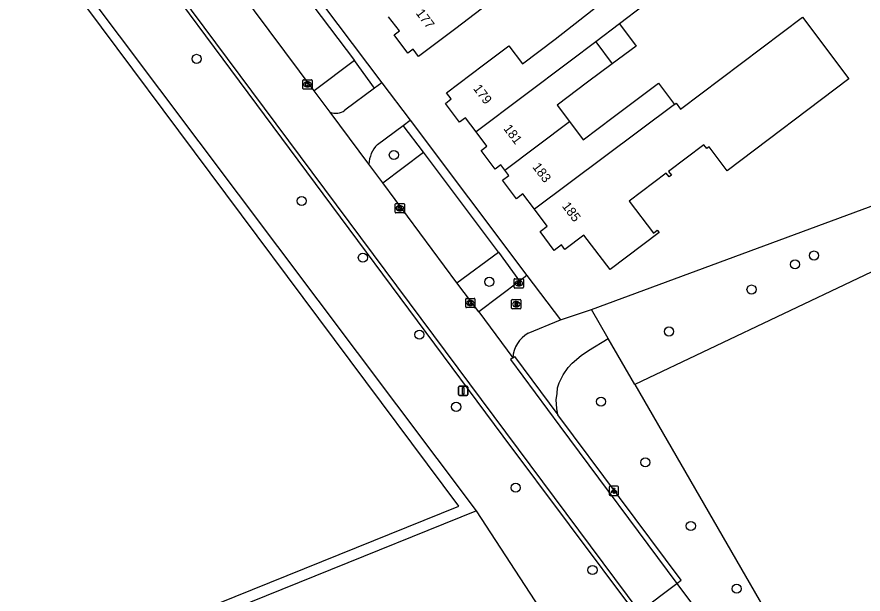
# Model space of a CAD drawing. Extents: x 164494 to 166241, y 382475 to 384494.
# Drawn here: x 165007.7 to 165098.7, y 383132.9 to 383195 of the extents above; entities that cross this region are included whole.
import ezdxf

# ---------------------------------------------------------------- set-up
doc = ezdxf.new("R2010")
doc.units = 0
for name, color, linetype in [('IMGEO_Berm_halfverhard', 7, 'Continuous'), ('IMGEO_Boom', 7, 'Continuous'), ('IMGEO_Bouwland', 7, 'Continuous'), ('IMGEO_Brandkraan', 7, 'Continuous'), ('IMGEO_Haag', 7, 'Continuous'), ('IMGEO_Hek', 7, 'Continuous'), ('IMGEO_Kolk', 7, 'Continuous'), ('IMGEO_Lichtpunt', 7, 'Continuous'), ('IMGEO_Loofbos', 7, 'Continuous'), ('IMGEO_Pand', 7, 'Continuous'), ('IMGEO_Pand_nummerreeks', 7, 'Continuous'), ('IMGEO_Parkeervlak_open', 7, 'Continuous'), ('IMGEO_Rijbaan_lokaal_gesloten', 7, 'Continuous'), ('IMGEO_Rijbaan_lokaal_onverhard', 7, 'Continuous'), ('IMGEO_Rioolput', 7, 'Continuous'), ('IMGEO_Verkeersbordpaal', 7, 'Continuous'), ('IMGEO_Voetpad_open', 7, 'Continuous')]:
    doc.layers.add(name, color=color, linetype=linetype)

msp = doc.modelspace()

# ---------------------------------------------------------------- linework, layer by layer
at = {"layer": 'IMGEO_Berm_halfverhard'}
for points in [[(165010.162, 383216.934), (165012.663, 383213.574), (165041.519, 383174.67), (165059.934, 383149.875), (165074.189, 383130.821), (165074.54, 383131.069)], [(165078.641, 383134.022), (165079.122, 383134.381), (165065.842, 383152.183)]]:
    msp.add_lwpolyline(points, dxfattribs=at)
at = {"layer": 'IMGEO_Boom'}
for centre in [(165027.003, 383190.44), (165048.216, 383180.108), (165038.31, 383175.163), (165044.883, 383169.068), (165093.391, 383169.297), (165091.349, 383168.347), (165058.474, 383166.472), (165086.672, 383165.641), (165050.966, 383160.792), (165077.792, 383161.13), (165070.494, 383153.587), (165054.914, 383153.031), (165075.248, 383147.061), (165061.314, 383144.337), (165080.143, 383140.228), (165069.575, 383135.482), (165085.071, 383133.473)]:
    msp.add_circle(centre, 0.489, dxfattribs=at)
at = {"layer": 'IMGEO_Bouwland'}
msp.add_lwpolyline([(165074.123, 383155.419), (165090.977, 383126.271)], dxfattribs=at)
at = {"layer": 'IMGEO_Brandkraan'}
for p, q in [((165061.145, 383165.879), (165061.145, 383166.731)), ((165061.22, 383166.805), (165062.072, 383166.805)), ((165061.633, 383166.585), (165061.658, 383166.585)), ((165062.146, 383166.731), (165062.146, 383165.879)), ((165062.072, 383165.805), (165061.22, 383165.805)), ((165061.656, 383166.025), (165061.631, 383166.025))]:
    msp.add_line(p, q, dxfattribs=at)
for points in [[(165061.145, 383165.879), (165061.145, 383166.731)], [(165061.22, 383166.805), (165062.072, 383166.805)], [(165062.146, 383166.731), (165062.146, 383165.879)], [(165062.072, 383165.805), (165061.22, 383165.805)], [(165061.493, 383166.505), (165061.493, 383166.105), (165061.706, 383166.105)], [(165061.724, 383166.505), (165061.493, 383166.505)], [(165061.672, 383166.424), (165061.618, 383166.424), (165061.618, 383166.348)], [(165061.618, 383166.348), (165061.671, 383166.348)], [(165061.68, 383166.272), (165061.618, 383166.272), (165061.618, 383166.191)], [(165061.618, 383166.191), (165061.68, 383166.191)]]:
    msp.add_lwpolyline(points, dxfattribs=at)
for centre, radius, start, end in [((165061.222, 383166.729), 0.0765, 91.55205, 178.44795), ((165061.222, 383166.729), 0.0765, 91.55205, 178.44795), ((165062.07, 383166.729), 0.0765, 1.55205, 88.44795), ((165062.07, 383166.729), 0.0765, 1.55205, 88.44795), ((165061.222, 383165.881), 0.0765, 181.55205, 268.44795), ((165061.222, 383165.881), 0.0765, 181.55205, 268.44795), ((165061.673, 383166.386), 0.0379, 267.82845, 90.93552), ((165061.681, 383166.231), 0.0404, 269.87594, 90.50774), ((165061.712, 383166.356), 0.251, 268.66757, 293.53466), ((165061.728, 383166.36), 0.145, 59.4692, 91.53667), ((165061.753, 383166.407), 0.0922, 285.51372, 58.15012), ((165061.758, 383166.215), 0.105, 301.31148, 78.98903), ((165062.07, 383165.881), 0.0765, 271.55205, 358.44795), ((165062.07, 383165.881), 0.0765, 271.55205, 358.44795)]:
    msp.add_arc(centre, radius, start, end, dxfattribs=at)
for centre, major_axis, ratio, start_param, end_param in [((165061.632, 383166.305), (-0.387, 0.002), 0.722429, 4.712389, 7.853982), ((165061.657, 383166.305), (-0.39, 0.002), 0.717154, 1.570796, 4.712389)]:
    msp.add_ellipse(centre, major_axis=major_axis, ratio=ratio, start_param=start_param, end_param=end_param, dxfattribs=at)
at = {"layer": 'IMGEO_Haag'}
for points in [[(165057.111, 383141.834), (165001.652, 383215.597)], [(164990.882, 383140.55), (164991.336, 383140.194), (164999.033, 383132.273), (165005.383, 383122.26), (165055.217, 383142.364), (165001.686, 383214.058), (164971.559, 383197.218), (164924.278, 383170.366), (164950.628, 383163.159), (164961.434, 383158.935), (164968.553, 383155.492), (164979.763, 383149.202)], [(165057.111, 383141.834), (165004.905, 383120.773)]]:
    msp.add_lwpolyline(points, dxfattribs=at)
at = {"layer": 'IMGEO_Hek'}
for points in [[(165005.383, 383122.26), (165055.217, 383142.364), (165001.686, 383214.058), (164971.559, 383197.218), (164924.278, 383170.366), (164950.628, 383163.159), (164961.434, 383158.935), (164968.553, 383155.492), (164979.763, 383149.202)], [(165069.455, 383163.492), (165113.129, 383179.617), (165117.672, 383182.875)]]:
    msp.add_lwpolyline(points, dxfattribs=at)
at = {"layer": 'IMGEO_Kolk'}
for p, q in [((165038.433, 383187.271), (165038.433, 383188.123)), ((165038.508, 383188.197), (165039.36, 383188.197)), ((165038.921, 383187.977), (165038.946, 383187.977)), ((165039.434, 383188.123), (165039.434, 383187.271)), ((165039.36, 383187.197), (165038.508, 383187.197)), ((165038.944, 383187.417), (165038.919, 383187.417)), ((165048.36, 383173.953), (165048.36, 383174.805)), ((165048.435, 383174.879), (165049.287, 383174.879)), ((165049.361, 383174.805), (165049.361, 383173.953)), ((165049.287, 383173.879), (165048.435, 383173.879)), ((165048.871, 383174.099), (165048.846, 383174.099)), ((165048.848, 383174.659), (165048.873, 383174.659)), ((165055.937, 383163.768), (165055.937, 383164.62)), ((165056.012, 383164.694), (165056.864, 383164.694)), ((165056.448, 383163.914), (165056.423, 383163.914)), ((165056.425, 383164.474), (165056.45, 383164.474)), ((165056.938, 383164.62), (165056.938, 383163.768)), ((165056.864, 383163.694), (165056.012, 383163.694))]:
    msp.add_line(p, q, dxfattribs=at)
for points in [[(165038.433, 383187.271), (165038.433, 383188.123)], [(165038.508, 383188.197), (165039.36, 383188.197)], [(165038.754, 383187.897), (165038.877, 383187.897), (165038.877, 383187.746), (165039.007, 383187.897), (165039.171, 383187.897), (165039.025, 383187.746), (165039.178, 383187.497), (165039.026, 383187.497), (165038.941, 383187.661), (165038.877, 383187.594), (165038.877, 383187.497), (165038.754, 383187.497), (165038.754, 383187.897)], [(165039.434, 383188.123), (165039.434, 383187.271)], [(165039.36, 383187.197), (165038.508, 383187.197)], [(165048.36, 383173.953), (165048.36, 383174.805)], [(165048.435, 383174.879), (165049.287, 383174.879)], [(165049.361, 383174.805), (165049.361, 383173.953)], [(165049.287, 383173.879), (165048.435, 383173.879)], [(165048.681, 383174.579), (165048.804, 383174.579), (165048.804, 383174.428), (165048.934, 383174.579), (165049.098, 383174.579), (165048.952, 383174.428), (165049.105, 383174.179), (165048.953, 383174.179), (165048.868, 383174.343), (165048.804, 383174.276), (165048.804, 383174.179), (165048.681, 383174.179), (165048.681, 383174.579)], [(165055.937, 383163.768), (165055.937, 383164.62)], [(165056.012, 383164.694), (165056.864, 383164.694)], [(165056.258, 383164.394), (165056.381, 383164.394), (165056.381, 383164.243), (165056.511, 383164.394), (165056.675, 383164.394), (165056.529, 383164.243), (165056.682, 383163.994), (165056.53, 383163.994), (165056.445, 383164.158), (165056.381, 383164.091), (165056.381, 383163.994), (165056.258, 383163.994), (165056.258, 383164.394)], [(165056.938, 383164.62), (165056.938, 383163.768)], [(165056.864, 383163.694), (165056.012, 383163.694)]]:
    msp.add_lwpolyline(points, dxfattribs=at)
for centre, start, end in [((165038.51, 383188.121), 91.55205, 178.44795), ((165038.51, 383188.121), 91.55205, 178.44795), ((165039.358, 383188.121), 1.55205, 88.44795), ((165039.358, 383188.121), 1.55205, 88.44795), ((165038.51, 383187.273), 181.55205, 268.44795), ((165038.51, 383187.273), 181.55205, 268.44795), ((165039.358, 383187.273), 271.55205, 358.44795), ((165039.358, 383187.273), 271.55205, 358.44795), ((165048.437, 383174.803), 91.55205, 178.44795), ((165048.437, 383174.803), 91.55205, 178.44795), ((165049.285, 383174.803), 1.55205, 88.44795), ((165049.285, 383174.803), 1.55205, 88.44795), ((165048.437, 383173.955), 181.55205, 268.44795), ((165048.437, 383173.955), 181.55205, 268.44795), ((165049.285, 383173.955), 271.55205, 358.44795), ((165049.285, 383173.955), 271.55205, 358.44795), ((165056.014, 383164.618), 91.55205, 178.44795), ((165056.014, 383164.618), 91.55205, 178.44795), ((165056.862, 383164.618), 1.55205, 88.44795), ((165056.862, 383164.618), 1.55205, 88.44795), ((165056.014, 383163.77), 181.55205, 268.44795), ((165056.014, 383163.77), 181.55205, 268.44795), ((165056.862, 383163.77), 271.55205, 358.44795), ((165056.862, 383163.77), 271.55205, 358.44795)]:
    msp.add_arc(centre, 0.0765, start, end, dxfattribs=at)
for centre, major_axis, ratio, start_param, end_param in [((165038.92, 383187.697), (-0.387, 0.002), 0.722429, 4.712389, 7.853982), ((165038.945, 383187.697), (-0.39, 0.002), 0.717154, 1.570796, 4.712389), ((165048.847, 383174.379), (-0.387, 0.002), 0.722429, 4.712389, 7.853982), ((165048.872, 383174.379), (-0.39, 0.002), 0.717154, 1.570796, 4.712389), ((165056.424, 383164.194), (-0.387, 0.002), 0.722429, 4.712389, 7.853982), ((165056.449, 383164.194), (-0.39, 0.002), 0.717154, 1.570796, 4.712389)]:
    msp.add_ellipse(centre, major_axis=major_axis, ratio=ratio, start_param=start_param, end_param=end_param, dxfattribs=at)
at = {"layer": 'IMGEO_Lichtpunt'}
for p, q in [((165071.376, 383144.402), (165071.376, 383143.595)), ((165071.376, 383144.402), (165071.376, 383143.595)), ((165072.278, 383144.497), (165071.47, 383144.497)), ((165072.278, 383144.497), (165071.47, 383144.497)), ((165072.372, 383143.595), (165072.372, 383144.402)), ((165072.372, 383143.595), (165072.372, 383144.402)), ((165071.47, 383143.501), (165072.278, 383143.501)), ((165071.47, 383143.501), (165072.278, 383143.501))]:
    msp.add_line(p, q, dxfattribs=at)
for points in [[(165071.75, 383144.066), (165071.789, 383144.038), (165071.601, 383143.776), (165071.563, 383143.803), (165071.75, 383144.066)], [(165071.852, 383144.018), (165071.899, 383144.018), (165071.899, 383143.696), (165071.852, 383143.696), (165071.852, 383144.018)], [(165071.962, 383144.038), (165072, 383144.065), (165072.187, 383143.803), (165072.148, 383143.775), (165071.962, 383144.038)]]:
    msp.add_lwpolyline(points, dxfattribs=at)
msp.add_circle((165071.875, 383144.2), 0.0994, dxfattribs=at)
for centre, start, end in [((165071.47, 383144.402), 90, 180), ((165071.47, 383144.402), 90, 180), ((165072.278, 383144.402), 0, 90), ((165072.278, 383144.402), 0, 90), ((165071.47, 383143.595), 180, 270), ((165071.47, 383143.595), 180, 270), ((165072.278, 383143.595), 270, 0), ((165072.278, 383143.595), 270, 360)]:
    msp.add_arc(centre, 0.0946, start, end, dxfattribs=at)
at = {"layer": 'IMGEO_Loofbos'}
for points in [[(165140.014, 383207.007), (165122.086, 383178.215), (165074.123, 383155.419)], [(165069.455, 383163.492), (165113.129, 383179.617), (165117.672, 383182.875), (165120.913, 383186.942)], [(165074.123, 383155.419), (165071.264, 383160.363)], [(165064.424, 383130.625), (165057.111, 383141.834)]]:
    msp.add_lwpolyline(points, dxfattribs=at)
at = {"layer": 'IMGEO_Pand'}
for points in [[(165057.061, 383182.578), (165055.907, 383184.106), (165055.28, 383183.633), (165053.752, 383185.657), (165054.378, 383186.13), (165053.869, 383186.804), (165057.867, 383189.808), (165060.586, 383191.852), (165062.046, 383189.909), (165065.549, 383192.541), (165073.025, 383198.419), (165078.583, 383202.656), (165076.095, 383206.151), (165083.664, 383211.659), (165087.792, 383205.569), (165075.031, 383196.131), (165072.484, 383194.21)], [(165063.52, 383206.844), (165065.122, 383208.035), (165066.933, 383205.599), (165059.726, 383200.352), (165061.149, 383198.459), (165057.586, 383195.781), (165054.871, 383193.698), (165050.874, 383190.694), (165050.291, 383191.47), (165049.732, 383191.049), (165048.25, 383193.021), (165048.81, 383193.441), (165047.656, 383194.976)], [(165078.372, 383185.544), (165078.553, 383185.68), (165079.047, 383185.026), (165092.15, 383194.924), (165097.149, 383188.306), (165084.045, 383178.409), (165082.1, 383180.984), (165081.853, 383180.797), (165081.545, 383181.204), (165077.747, 383178.336), (165078.054, 383177.929), (165077.807, 383177.742), (165077.499, 383178.149), (165073.526, 383175.147), (165076.129, 383171.7), (165076.536, 383172.007), (165076.723, 383171.76), (165071.456, 383167.782), (165068.654, 383171.493), (165066.603, 383169.944), (165066.234, 383170.432), (165065.461, 383169.848), (165063.937, 383171.865), (165064.71, 383172.45), (165063.327, 383174.281)], [(165072.484, 383194.21), (165069.932, 383192.285)], [(165072.484, 383194.21), (165074.266, 383191.803), (165071.696, 383189.901)], [(165069.932, 383192.285), (165067.16, 383190.195), (165057.061, 383182.578)], [(165069.932, 383192.285), (165071.696, 383189.901)], [(165071.696, 383189.901), (165069.021, 383187.921), (165065.758, 383185.469), (165067.089, 383183.698)], [(165067.089, 383183.698), (165068.56, 383181.741), (165071.802, 383184.178), (165076.657, 383187.826), (165078.372, 383185.544)], [(165078.372, 383185.544), (165063.327, 383174.281)], [(165060.161, 383178.473), (165067.089, 383183.698)], [(165060.161, 383178.473), (165059.728, 383179.046), (165059.102, 383178.573), (165057.593, 383180.571), (165058.22, 383181.044), (165057.061, 383182.578)], [(165063.327, 383174.281), (165062.085, 383175.926), (165061.398, 383175.407), (165059.901, 383177.389), (165060.588, 383177.908), (165060.161, 383178.473)]]:
    msp.add_lwpolyline(points, dxfattribs=at)
at = {"layer": 'IMGEO_Parkeervlak_open'}
for points in [[(165043.994, 383190.272), (165039.657, 383187.007)], [(165047.015, 383177.125), (165051.395, 383180.401)], [(165054.99, 383166.374), (165059.454, 383169.659)], [(165062.528, 383167.161), (165066.135, 383162.372)], [(165061.726, 383166.554), (165057.36, 383163.251)]]:
    msp.add_lwpolyline(points, dxfattribs=at)
at = {"layer": 'IMGEO_Rijbaan_lokaal_gesloten'}
for points in [[(164958.624, 383286.837), (164967.779, 383274.687), (165004.939, 383224.601), (165007.308, 383221.332), (165010.834, 383216.638), (165074.54, 383131.069)], [(165039.657, 383187.007), (165031.646, 383197.767)], [(165041.362, 383184.698), (165039.657, 383187.007)], [(165045.531, 383179.12), (165041.362, 383184.698)], [(165047.015, 383177.125), (165045.531, 383179.12)], [(165054.99, 383166.374), (165047.015, 383177.125)], [(165057.36, 383163.251), (165054.99, 383166.374)], [(165057.36, 383163.251), (165061.002, 383158.295)], [(165061.002, 383158.295), (165060.749, 383158.104), (165066.076, 383150.934), (165078.641, 383134.022)], [(165074.593, 383130.998), (165078.641, 383134.022)], [(165078.641, 383134.022), (165086.849, 383123.029)]]:
    msp.add_lwpolyline(points, dxfattribs=at)
at = {"layer": 'IMGEO_Rijbaan_lokaal_onverhard'}
for points in [[(165066.135, 383162.372), (165069.455, 383163.492)], [(165071.264, 383160.363), (165069.455, 383163.492)], [(165062.645, 383160.938), (165066.135, 383162.372)], [(165065.842, 383152.183), (165065.74, 383152.848), (165065.68, 383153.791), (165065.758, 383154.474), (165065.827, 383155.087), (165065.993, 383155.616), (165066.406, 383156.474), (165066.958, 383157.262), (165067.377, 383157.726), (165068.351, 383158.548), (165069.136, 383159.073), (165071.264, 383160.363)], [(165061.002, 383158.295), (165061.194, 383158.439), (165065.842, 383152.183)]]:
    msp.add_lwpolyline(points, dxfattribs=at)
msp.add_arc((165064.3, 383158.077), 3.305, 120.04876, 176.2176, dxfattribs=at)
at = {"layer": 'IMGEO_Rioolput'}
for p, q in [((165060.881, 383163.641), (165060.881, 383164.493)), ((165060.956, 383164.567), (165061.808, 383164.567)), ((165061.369, 383164.347), (165061.394, 383164.347)), ((165061.882, 383164.493), (165061.882, 383163.641)), ((165061.808, 383163.567), (165060.956, 383163.567)), ((165061.392, 383163.787), (165061.367, 383163.787))]:
    msp.add_line(p, q, dxfattribs=at)
for points in [[(165060.881, 383163.641), (165060.881, 383164.493)], [(165060.956, 383164.567), (165061.808, 383164.567)], [(165061.47, 383164.265), (165061.218, 383164.267), (165061.218, 383163.867)], [(165061.218, 383163.867), (165061.342, 383163.867), (165061.342, 383164.029), (165061.353, 383164.029)], [(165061.396, 383164.186), (165061.342, 383164.186), (165061.342, 383164.105)], [(165061.342, 383164.105), (165061.394, 383164.105)], [(165061.4, 383164), (165061.471, 383163.867), (165061.611, 383163.867), (165061.546, 383163.993)], [(165061.882, 383164.493), (165061.882, 383163.641)], [(165061.808, 383163.567), (165060.956, 383163.567)]]:
    msp.add_lwpolyline(points, dxfattribs=at)
for centre, radius, start, end in [((165060.958, 383164.491), 0.0765, 91.55205, 178.44795), ((165060.958, 383164.491), 0.0765, 91.55205, 178.44795), ((165061.352, 383163.976), 0.0533, 26.02933, 88.69889), ((165061.378, 383164.294), 0.19, 274.7715, 282.96867), ((165061.402, 383164.09), 0.0964, 77.00612, 93.18647), ((165061.416, 383164.147), 0.0378, 276.66336, 79.67722), ((165061.469, 383164.155), 0.109, 350.36119, 89.41601), ((165061.467, 383164.155), 0.112, 277.58423, 350.98172), ((165061.451, 383163.94), 0.108, 29.51342, 73.79051), ((165061.806, 383164.491), 0.0765, 1.55205, 88.44795), ((165061.806, 383164.491), 0.0765, 1.55205, 88.44795), ((165060.958, 383163.643), 0.0765, 181.55205, 268.44795), ((165060.958, 383163.643), 0.0765, 181.55205, 268.44795), ((165061.806, 383163.643), 0.0765, 271.55205, 358.44795), ((165061.806, 383163.643), 0.0765, 271.55205, 358.44795)]:
    msp.add_arc(centre, radius, start, end, dxfattribs=at)
for centre, major_axis, ratio, start_param, end_param in [((165061.368, 383164.067), (-0.387, 0.002), 0.722429, 4.712389, 7.853982), ((165061.393, 383164.067), (-0.39, 0.002), 0.717154, 1.570796, 4.712389)]:
    msp.add_ellipse(centre, major_axis=major_axis, ratio=ratio, start_param=start_param, end_param=end_param, dxfattribs=at)
at = {"layer": 'IMGEO_Verkeersbordpaal'}
for p, q in [((165055.181, 383154.349), (165055.181, 383155.149)), ((165055.181, 383155.149), (165055.181, 383154.349)), ((165055.281, 383155.249), (165056.071, 383155.249)), ((165056.071, 383155.249), (165055.281, 383155.249)), ((165056.171, 383155.149), (165056.171, 383154.349)), ((165056.171, 383154.349), (165056.171, 383155.149)), ((165056.071, 383154.249), (165055.281, 383154.249)), ((165055.281, 383154.249), (165056.071, 383154.249))]:
    msp.add_line(p, q, dxfattribs=at)
msp.add_lwpolyline([(165055.601, 383155.124), (165055.751, 383155.124), (165055.751, 383154.374), (165055.601, 383154.374), (165055.601, 383155.124)], dxfattribs=at)
for centre, start, end in [((165055.281, 383155.149), 90, 180), ((165055.281, 383155.149), 90, 180), ((165056.071, 383155.149), 0, 90), ((165056.071, 383155.149), 360, 90), ((165055.281, 383154.349), 180, 270), ((165055.281, 383154.349), 180, 270), ((165056.071, 383154.349), 270, 0), ((165056.071, 383154.349), 270, 0)]:
    msp.add_arc(centre, 0.1, start, end, dxfattribs=at)
at = {"layer": 'IMGEO_Voetpad_open'}
for points in [[(165034.273, 383204.678), (165046.93, 383187.872)], [(165035.91, 383200.939), (165043.994, 383190.272)], [(165046.148, 383187.292), (165043.994, 383190.272)], [(165046.93, 383187.872), (165046.148, 383187.292)], [(165046.93, 383187.872), (165049.957, 383183.853)], [(165046.148, 383187.292), (165042.937, 383184.911)], [(165046.456, 383181.223), (165049.207, 383183.29)], [(165049.207, 383183.29), (165049.957, 383183.853)], [(165051.395, 383180.401), (165049.207, 383183.29)], [(165049.957, 383183.853), (165062.528, 383167.161)], [(165059.454, 383169.659), (165051.395, 383180.401)], [(165059.454, 383169.659), (165061.726, 383166.554)], [(165062.528, 383167.161), (165061.726, 383166.554)]]:
    msp.add_lwpolyline(points, dxfattribs=at)
for centre, radius, start, end in [((165041.952, 383186.268), 1.677, 249.41318, 305.99051), ((165048.637, 383179.009), 3.108, 134.56655, 177.94907)]:
    msp.add_arc(centre, radius, start, end, dxfattribs=at)

# ---------------------------------------------------------------- texts
at = {"layer": 'IMGEO_Pand_nummerreeks'}
for s, rotation, p in [('177', 306.92692, (165050.525, 383195.351)), ('179', 307.06443, (165056.695, 383187.243)), ('181', 307.06443, (165059.947, 383182.937)), ('183', 307.06443, (165063.062, 383178.813)), ('185', 307.06443, (165066.245, 383174.598))]:
    msp.add_text(s, height=1, rotation=rotation, dxfattribs=at).set_placement(p)

doc.saveas('drawing.dxf')
